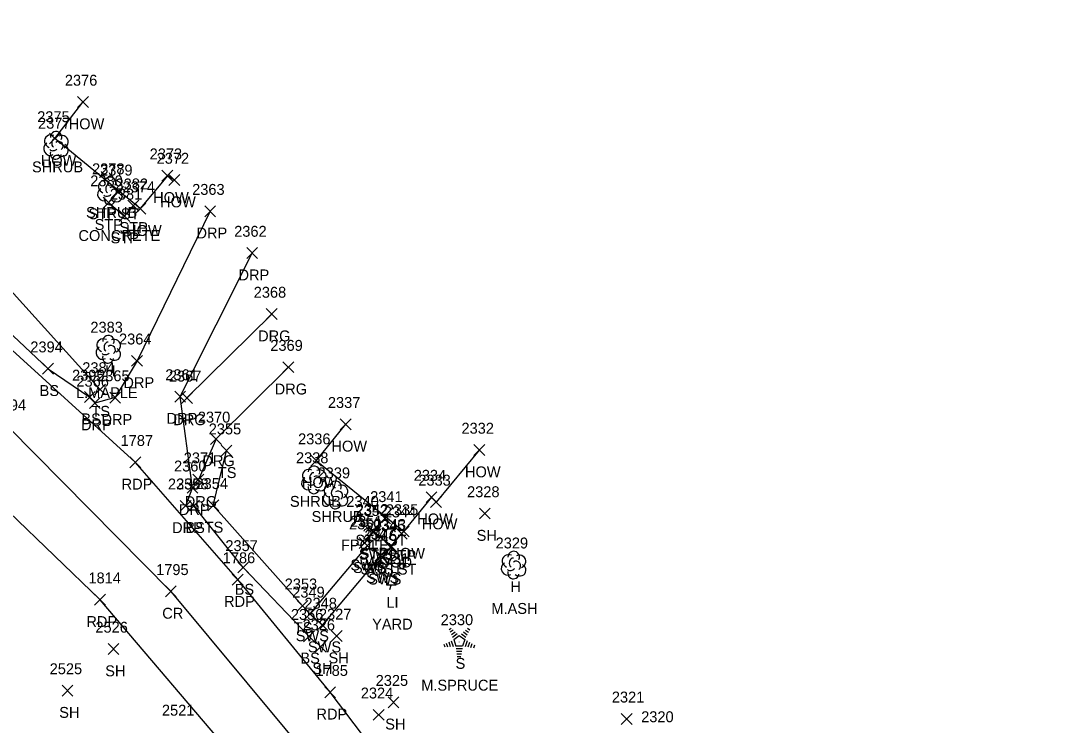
# Model space of a CAD drawing. Extents: x 1634209 to 1639641, y 608564 to 612258.
# Drawn here: x 1638878.7 to 1639067, y 611582.6 to 611711.9 of the extents above; entities that cross this region are included whole.
import ezdxf

# ---------------------------------------------------------------- set-up
doc = ezdxf.new("R2010")
doc.units = 0
for name, color, linetype in [('L_A', 7, 'Continuous'), ('L_C', 7, 'Continuous'), ('L_I', 7, 'Continuous'), ('L_TIC', 7, 'Continuous'), ('LBC', 7, 'Continuous'), ('LBF', 7, 'Continuous'), ('LELB', 7, 'Continuous'), ('LFP', 7, 'Continuous'), ('LSH', 7, 'Continuous'), ('LTC', 7, 'Continuous'), ('LTD', 7, 'Continuous'), ('P_A', 7, 'Continuous'), ('P_I', 7, 'Continuous'), ('P_TIC', 7, 'Continuous'), ('PET', 7, 'Continuous'), ('PRC', 7, 'Continuous'), ('R_A', 7, 'Continuous'), ('R_I', 7, 'Continuous'), ('R_TIC', 7, 'Continuous'), ('RDG', 7, 'Continuous'), ('RDP', 7, 'Continuous'), ('RSW', 7, 'Continuous'), ('U_A', 7, 'Continuous'), ('U_C', 7, 'Continuous'), ('U_I', 7, 'Continuous'), ('ULP', 7, 'Continuous')]:
    doc.layers.add(name, color=color, linetype=linetype)

msp = doc.modelspace()

# ---------------------------------------------------------------- linework, layer by layer
at = {"layer": 'L_TIC'}
for points in [[(1638889.13, 611695.92), (1638891.13, 611697.92)], [(1638891.13, 611695.92), (1638889.13, 611697.92)], [(1638884, 611689.23), (1638886, 611691.23)], [(1638886, 611689.23), (1638884, 611691.23)], [(1638904.62, 611682.41), (1638906.62, 611684.41)], [(1638906.62, 611682.41), (1638904.62, 611684.41)], [(1638905.9, 611681.61), (1638907.9, 611683.61)], [(1638907.9, 611681.61), (1638905.9, 611683.61)], [(1638895.54, 611679.44), (1638897.54, 611681.44)], [(1638897.54, 611679.44), (1638895.54, 611681.44)], [(1638893.81, 611677.47), (1638895.81, 611679.47)], [(1638895.81, 611677.47), (1638893.81, 611679.47)], [(1638898.37, 611676.9), (1638900.37, 611678.9)], [(1638900.37, 611676.9), (1638898.37, 611678.9)], [(1638899.64, 611676.37), (1638901.64, 611678.37)], [(1638901.64, 611676.37), (1638899.64, 611678.37)], [(1638896.75, 611675.02), (1638898.75, 611677.02)], [(1638898.75, 611675.02), (1638896.75, 611677.02)], [(1638882.74, 611647.02), (1638884.74, 611649.02)], [(1638884.74, 611647.02), (1638882.74, 611649.02)], [(1638892.27, 611643.21), (1638894.27, 611645.21)], [(1638894.27, 611643.21), (1638892.27, 611645.21)], [(1638890.39, 611641.83), (1638892.39, 611643.83)], [(1638892.39, 611641.83), (1638890.39, 611643.83)], [(1638937.3, 611636.83), (1638939.3, 611638.83)], [(1638939.3, 611636.83), (1638937.3, 611638.83)], [(1638915.45, 611631.98), (1638917.45, 611633.98)], [(1638917.45, 611631.98), (1638915.45, 611633.98)], [(1638961.79, 611632.11), (1638963.79, 611634.11)], [(1638963.79, 611632.11), (1638961.79, 611634.11)], [(1638931.88, 611630.16), (1638933.88, 611632.16)], [(1638933.88, 611630.16), (1638931.88, 611632.16)], [(1638953.04, 611623.48), (1638955.04, 611625.48)], [(1638955.04, 611623.48), (1638953.04, 611625.48)], [(1638953.88, 611622.58), (1638955.88, 611624.58)], [(1638955.88, 611622.58), (1638953.88, 611624.58)], [(1638909.47, 611621.91), (1638911.47, 611623.91)], [(1638911.47, 611621.91), (1638909.47, 611623.91)], [(1638913.03, 611621.96), (1638915.03, 611623.96)], [(1638915.03, 611621.96), (1638913.03, 611623.96)], [(1638962.82, 611620.47), (1638964.82, 611622.47)], [(1638964.82, 611620.47), (1638962.82, 611622.47)], [(1638944.49, 611619.57), (1638946.49, 611621.57)], [(1638946.49, 611619.57), (1638944.49, 611621.57)], [(1638942.42, 611617.21), (1638944.42, 611619.21)], [(1638944.42, 611617.21), (1638942.42, 611619.21)], [(1638947.55, 611616.76), (1638949.55, 611618.76)], [(1638949.55, 611616.76), (1638947.55, 611618.76)], [(1638947.92, 611617.17), (1638949.92, 611619.17)], [(1638949.92, 611617.17), (1638947.92, 611619.17)], [(1638945.66, 611614.46), (1638947.66, 611616.46)], [(1638947.66, 611614.46), (1638945.66, 611616.46)], [(1638918.5, 611610.58), (1638920.5, 611612.58)], [(1638920.5, 611610.58), (1638918.5, 611612.58)], [(1638929.38, 611603.55), (1638931.38, 611605.55)], [(1638931.38, 611603.55), (1638929.38, 611605.55)], [(1638930.56, 611597.97), (1638932.56, 611599.97)], [(1638932.56, 611597.97), (1638930.56, 611599.97)], [(1638935.66, 611598.01), (1638937.66, 611600.01)], [(1638937.66, 611598.01), (1638935.66, 611600.01)], [(1638932.71, 611596.06), (1638934.71, 611598.06)], [(1638934.71, 611596.06), (1638932.71, 611598.06)], [(1638894.73, 611595.63), (1638896.73, 611597.63)], [(1638896.73, 611595.63), (1638894.73, 611597.63)], [(1638886.29, 611588.01), (1638888.29, 611590.01)], [(1638888.29, 611588.01), (1638886.29, 611590.01)], [(1638946.06, 611585.87), (1638948.06, 611587.87)], [(1638948.06, 611585.87), (1638946.06, 611587.87)], [(1638943.33, 611583.56), (1638945.33, 611585.56)], [(1638945.33, 611583.56), (1638943.33, 611585.56)], [(1638988.8, 611582.82), (1638990.8, 611584.82)], [(1638990.8, 611582.82), (1638988.8, 611584.82)]]:
    msp.add_lwpolyline(points, dxfattribs=at)
at = {"layer": 'LBC'}
for points in [[(1638906.9, 611682.61), (1638905.62, 611683.41), (1638900.64, 611677.37), (1638885, 611690.23), (1638890.13, 611696.92)], [(1638962.79, 611633.11), (1638954.88, 611623.58), (1638954.04, 611624.48), (1638948.92, 611618.17), (1638932.88, 611631.16), (1638938.3, 611637.83)]]:
    msp.add_lwpolyline(points, dxfattribs=at)
at = {"layer": 'LBF'}
for points in [[(1638896.54, 611680.44), (1638894.81, 611678.47), (1638897.75, 611676.02), (1638899.37, 611677.9)], [(1638945.49, 611620.57), (1638943.42, 611618.21), (1638946.66, 611615.46), (1638948.55, 611617.76)]]:
    msp.add_lwpolyline(points, dxfattribs=at)
at = {"layer": 'LELB'}
for points in [[(1638873.21, 611711.86), (1638857.7, 611692.03), (1638852.16, 611680.32), (1638857.49, 611671.46), (1638870.87, 611660.12), (1638883.74, 611648.02), (1638891.39, 611642.83)], [(1638893.27, 611644.21), (1638875.11, 611664.31), (1638860.57, 611677.05), (1638859.03, 611684.68), (1638875.95, 611708.58)], [(1638930.38, 611604.55), (1638914.03, 611622.96), (1638916.45, 611632.98)], [(1638931.56, 611598.97), (1638919.5, 611611.58), (1638910.47, 611622.91)]]:
    msp.add_lwpolyline(points, dxfattribs=at)
at = {"layer": 'LFP'}
for radius in [0.625, 0.0833]:
    msp.add_circle((1638941.77, 611619.69), radius, dxfattribs=at)
at = {"layer": 'LSH'}
for p, q in [((1638885.16, 611689.03), (1638885.16, 611689.03)), ((1638885.16, 611689.03), (1638885.16, 611689.03)), ((1638895.06, 611680.68), (1638895.06, 611680.68)), ((1638895.06, 611680.68), (1638895.06, 611680.68)), ((1638932.45, 611627.7), (1638932.45, 611627.7)), ((1638932.45, 611627.7), (1638932.45, 611627.7)), ((1638936.42, 611624.92), (1638936.42, 611624.92)), ((1638936.42, 611624.92), (1638936.42, 611624.92))]:
    msp.add_line(p, q, dxfattribs=at)
for centre in [(1638885.2, 611690.46), (1638895.1, 611682.12), (1638932.5, 611629.13), (1638936.46, 611626.36)]:
    msp.add_arc(centre, 1.05, 335.5272, 180.9563, dxfattribs=at)
for centre, major_axis, ratio, start_param, end_param in [((1638884.36, 611689.69), (1.21, -0.51), 0.895232, 1.570796, 4.712389), ((1638884.95, 611689.48), (-0.208, -0.792), 0.645439, 3.141593, 6.283185), ((1638886.2, 611689.61), (-1.14, -0.48), 0.949671, 1.570796, 4.712389), ((1638884.07, 611688.32), (0.58, -1.04), 0.959034, 3.141593, 6.283185), ((1638884.7, 611688.28), (-0.625, -0.083), 0.423636, 0, 3.141593), ((1638885.66, 611688.86), (-0.5, 0.667), 0.989748, 3.141593, 6.283185), ((1638886.16, 611688.19), (-1.09, 0.79), 0.841452, 1.570796, 4.712389), ((1638885.16, 611687.53), (0.26, 1.06), 0.942809, 1.570796, 4.712389), ((1638894.26, 611681.35), (1.21, -0.51), 0.895232, 1.570796, 4.712389), ((1638893.97, 611679.98), (0.58, -1.04), 0.959034, 3.141593, 6.283185), ((1638894.85, 611681.14), (-0.208, -0.792), 0.645439, 3.141593, 6.283185), ((1638895.56, 611680.52), (-0.5, 0.667), 0.989748, 3.141593, 6.283185), ((1638896.1, 611681.27), (-1.14, -0.48), 0.949671, 1.570796, 4.712389), ((1638895.06, 611679.18), (0.26, 1.06), 0.942809, 1.570796, 4.712389), ((1638894.6, 611679.93), (-0.625, -0.083), 0.423636, 0, 3.141593), ((1638896.06, 611679.85), (-1.09, 0.79), 0.841452, 1.570796, 4.712389), ((1638931.66, 611628.36), (1.21, -0.51), 0.895232, 1.570796, 4.712389), ((1638932.24, 611628.16), (-0.208, -0.792), 0.645439, 3.141593, 6.283185), ((1638932.95, 611627.53), (-0.5, 0.667), 0.989748, 3.141593, 6.283185), ((1638933.49, 611628.28), (-1.14, -0.48), 0.949671, 1.570796, 4.712389), ((1638931.37, 611626.99), (0.58, -1.04), 0.959034, 3.141593, 6.283185), ((1638932.45, 611626.2), (0.26, 1.06), 0.942809, 1.570796, 4.712389), ((1638931.99, 611626.95), (-0.625, -0.083), 0.423636, 0, 3.141593), ((1638933.45, 611626.86), (-1.09, 0.79), 0.841452, 1.570796, 4.712389), ((1638935.62, 611625.59), (1.21, -0.51), 0.895232, 1.570796, 4.712389), ((1638936.21, 611625.38), (-0.208, -0.792), 0.645439, 3.141593, 6.283185), ((1638937.46, 611625.51), (-1.14, -0.48), 0.949671, 1.570796, 4.712389), ((1638935.33, 611624.22), (0.58, -1.04), 0.959034, 3.141593, 6.283185), ((1638936.92, 611624.76), (-0.5, 0.667), 0.989748, 3.141593, 6.283185), ((1638937.42, 611624.09), (-1.09, 0.79), 0.841452, 1.570796, 4.712389), ((1638936.42, 611623.42), (0.26, 1.06), 0.942809, 1.570796, 4.712389), ((1638935.96, 611624.17), (-0.625, -0.083), 0.423636, 0, 3.141593)]:
    msp.add_ellipse(centre, major_axis=major_axis, ratio=ratio, start_param=start_param, end_param=end_param, dxfattribs=at)
at = {"layer": 'LTC'}
for p, q in [((1638957.26, 611600.21), (1638957.62, 611600.47)), ((1638957.47, 611599.75), (1638958, 611600.13)), ((1638960.29, 611600.1), (1638960.84, 611599.71)), ((1638960.66, 611600.45), (1638961.08, 611600.15)), ((1638957.66, 611598.14), (1638957.99, 611597.12)), ((1638957.68, 611599.28), (1638958.38, 611599.79)), ((1638957.89, 611598.82), (1638958.77, 611599.45)), ((1638958.11, 611598.36), (1638959.13, 611599.1)), ((1638958.11, 611598.36), (1638958.5, 611597.17)), ((1638959.13, 611599.1), (1638960.12, 611598.37)), ((1638959.55, 611599.41), (1638960.36, 611598.82)), ((1638960.12, 611598.37), (1638959.73, 611597.17)), ((1638959.92, 611599.76), (1638960.6, 611599.26)), ((1638960.56, 611598.1), (1638960.22, 611597.06)), ((1638956.29, 611597.49), (1638956.45, 611597.02)), ((1638956.75, 611597.71), (1638956.96, 611597.06)), ((1638957.2, 611597.93), (1638957.48, 611597.09)), ((1638959.73, 611597.17), (1638958.5, 611597.17)), ((1638959.69, 611596.67), (1638958.55, 611596.67)), ((1638959.61, 611596.17), (1638958.62, 611596.17)), ((1638961.01, 611597.85), (1638960.72, 611596.96)), ((1638961.45, 611597.6), (1638961.21, 611596.87)), ((1638961.89, 611597.35), (1638961.71, 611596.77)), ((1638959.53, 611595.67), (1638958.69, 611595.67)), ((1638959.44, 611595.17), (1638958.77, 611595.17))]:
    msp.add_line(p, q, dxfattribs=at)
at = {"layer": 'LTD'}
for p, q in [((1638894.75, 611651.63), (1638894.75, 611651.63)), ((1638894.75, 611651.63), (1638894.75, 611651.63)), ((1638969.06, 611612.07), (1638969.06, 611612.07)), ((1638969.06, 611612.07), (1638969.06, 611612.07))]:
    msp.add_line(p, q, dxfattribs=at)
for centre in [(1638894.8, 611653.06), (1638969.11, 611613.5)]:
    msp.add_arc(centre, 1.05, 335.5272, 180.9563, dxfattribs=at)
for centre, major_axis, ratio, start_param, end_param in [((1638893.96, 611652.29), (1.21, -0.51), 0.895232, 1.570796, 4.712389), ((1638894.54, 611652.08), (-0.208, -0.792), 0.645439, 3.141593, 6.283185), ((1638895.79, 611652.21), (-1.14, -0.48), 0.949671, 1.570796, 4.712389), ((1638893.67, 611650.92), (0.58, -1.04), 0.959034, 3.141593, 6.283185), ((1638894.29, 611650.88), (-0.625, -0.083), 0.423636, 0, 3.141593), ((1638895.25, 611651.46), (-0.5, 0.667), 0.989748, 3.141593, 6.283185), ((1638895.75, 611650.79), (-1.09, 0.79), 0.841452, 1.570796, 4.712389), ((1638894.75, 611650.13), (0.26, 1.06), 0.942809, 1.570796, 4.712389), ((1638968.27, 611612.73), (1.21, -0.51), 0.895232, 1.570796, 4.712389), ((1638968.85, 611612.52), (-0.208, -0.792), 0.645439, 3.141593, 6.283185), ((1638970.1, 611612.65), (-1.14, -0.48), 0.949671, 1.570796, 4.712389), ((1638967.98, 611611.36), (0.58, -1.04), 0.959034, 3.141593, 6.283185), ((1638968.6, 611611.32), (-0.625, -0.083), 0.423636, 0, 3.141593), ((1638969.56, 611611.9), (-0.5, 0.667), 0.989748, 3.141593, 6.283185), ((1638970.06, 611611.23), (-1.09, 0.79), 0.841452, 1.570796, 4.712389), ((1638969.06, 611610.57), (0.26, 1.06), 0.942809, 1.570796, 4.712389)]:
    msp.add_ellipse(centre, major_axis=major_axis, ratio=ratio, start_param=start_param, end_param=end_param, dxfattribs=at)
at = {"layer": 'P_TIC'}
for points in [[(1638898.72, 611629.86), (1638900.72, 611631.86)], [(1638900.72, 611629.86), (1638898.72, 611631.86)], [(1638917.51, 611608.36), (1638919.51, 611610.36)], [(1638919.51, 611608.36), (1638917.51, 611610.36)], [(1638905.24, 611606.19), (1638907.24, 611608.19)], [(1638907.24, 611606.19), (1638905.24, 611608.19)], [(1638892.27, 611604.66), (1638894.27, 611606.66)], [(1638894.27, 611604.66), (1638892.27, 611606.66)], [(1638934.46, 611587.7), (1638936.46, 611589.7)], [(1638936.46, 611587.7), (1638934.46, 611589.7)]]:
    msp.add_lwpolyline(points, dxfattribs=at)
at = {"layer": 'PET'}
for points in [[(1639148.64, 611331.08), (1639142.07, 611329.18), (1639135.69, 611328.74), (1639125.69, 611331.14), (1639119.17, 611334.87), (1639114.18, 611340.56), (1639098.76, 611361.78), (1639080.31, 611387.33), (1639061.61, 611413.48), (1639039.15, 611444.21), (1639014.33, 611480.36), (1638988.41, 611516.9), (1638963.39, 611551.84), (1638935.46, 611588.7), (1638918.51, 611609.36), (1638899.72, 611630.86), (1638874.4, 611653.86), (1638846.55, 611674.46), (1638833.14, 611682.53), (1638823.86, 611689.16)], [(1639117.36, 611283.37), (1639114.12, 611301.89), (1639095.51, 611328.5), (1639070.51, 611363.26), (1639041.38, 611404.69), (1639011.57, 611446.4), (1638984.33, 611485.14), (1638954.17, 611527.49), (1638934.32, 611554.77), (1638918.88, 611575.58), (1638893.27, 611605.66), (1638868.11, 611629.83), (1638836.66, 611652.85), (1638812.43, 611667.63)]]:
    msp.add_lwpolyline(points, dxfattribs=at)
at = {"layer": 'PRC'}
msp.add_lwpolyline([(1638818.79, 611678.83), (1638843.97, 611663.34), (1638876.43, 611637.38), (1638906.24, 611607.19), (1638934.14, 611573.69), (1638965.3, 611531.42), (1638998.82, 611484.34), (1639033.82, 611434.48), (1639068.01, 611386.3), (1639093.94, 611350.49), (1639111.89, 611325.37), (1639129.22, 611302.76)], dxfattribs=at)
at = {"layer": 'R_TIC'}
for points in [[(1638912.45, 611675.9), (1638914.45, 611677.9)], [(1638914.45, 611675.9), (1638912.45, 611677.9)], [(1638920.16, 611668.22), (1638922.16, 611670.22)], [(1638922.16, 611668.22), (1638920.16, 611670.22)], [(1638923.75, 611657.04), (1638925.75, 611659.04)], [(1638925.75, 611657.04), (1638923.75, 611659.04)], [(1638899.05, 611648.47), (1638901.05, 611650.47)], [(1638901.05, 611648.47), (1638899.05, 611650.47)], [(1638926.79, 611647.3), (1638928.79, 611649.3)], [(1638928.79, 611647.3), (1638926.79, 611649.3)], [(1638895.04, 611641.73), (1638897.04, 611643.73)], [(1638897.04, 611641.73), (1638895.04, 611643.73)], [(1638906.96, 611641.92), (1638908.96, 611643.92)], [(1638908.96, 611641.92), (1638906.96, 611643.92)], [(1638908.2, 611641.67), (1638910.2, 611643.67)], [(1638910.2, 611641.67), (1638908.2, 611643.67)], [(1638891.3, 611640.73), (1638893.3, 611642.73)], [(1638893.3, 611640.73), (1638891.3, 611642.73)], [(1638913.54, 611634.15), (1638915.54, 611636.15)], [(1638915.54, 611634.15), (1638913.54, 611636.15)], [(1638910.3, 611626.67), (1638912.3, 611628.67)], [(1638912.3, 611626.67), (1638910.3, 611628.67)], [(1638909.22, 611625.18), (1638911.22, 611627.18)], [(1638911.22, 611625.18), (1638909.22, 611627.18)], [(1638907.98, 611621.88), (1638909.98, 611623.88)], [(1638909.98, 611621.88), (1638907.98, 611623.88)], [(1638942.35, 611617.03), (1638944.35, 611619.03)], [(1638944.35, 611617.03), (1638942.35, 611619.03)], [(1638940.79, 611615.05), (1638942.79, 611617.05)], [(1638942.79, 611615.05), (1638940.79, 611617.05)], [(1638941.27, 611614.57), (1638943.27, 611616.57)], [(1638943.27, 611614.57), (1638941.27, 611616.57)], [(1638945.53, 611614.28), (1638947.53, 611616.28)], [(1638947.53, 611614.28), (1638945.53, 611616.28)], [(1638943.66, 611612.73), (1638945.66, 611614.73)], [(1638945.66, 611612.73), (1638943.66, 611614.73)], [(1638944.06, 611612.46), (1638946.06, 611614.46)], [(1638946.06, 611612.46), (1638944.06, 611614.46)], [(1638930.77, 611602.06), (1638932.77, 611604.06)], [(1638932.77, 611602.06), (1638930.77, 611604.06)], [(1638933, 611600.02), (1638935, 611602.02)], [(1638935, 611600.02), (1638933, 611602.02)]]:
    msp.add_lwpolyline(points, dxfattribs=at)
at = {"layer": 'RDG'}
for points in [[(1638909.2, 611642.67), (1638924.75, 611658.04)], [(1638927.79, 611648.3), (1638914.54, 611635.15), (1638911.3, 611627.67)]]:
    msp.add_lwpolyline(points, dxfattribs=at)
at = {"layer": 'RDP'}
for points in [[(1638913.45, 611676.9), (1638900.05, 611649.47), (1638896.04, 611642.73), (1638892.3, 611641.73)], [(1638908.98, 611622.88), (1638910.22, 611626.18), (1638907.96, 611642.92), (1638921.16, 611669.22)]]:
    msp.add_lwpolyline(points, dxfattribs=at)
at = {"layer": 'RSW'}
msp.add_lwpolyline([(1638946.53, 611615.28), (1638945.06, 611613.46), (1638944.66, 611613.73), (1638934, 611601.02), (1638931.77, 611603.06), (1638942.27, 611615.57), (1638941.79, 611616.05), (1638943.35, 611618.03)], dxfattribs=at)
at = {"layer": 'ULP'}
for p, q in [((1638945.82, 611608.35), (1638945.82, 611610.02)), ((1638945.82, 611610.02), (1638947.49, 611610.02)), ((1638946.82, 611610.85), (1638946.66, 611610.02)), ((1638947.49, 611610.02), (1638947.49, 611608.35)), ((1638947.49, 611608.35), (1638945.82, 611608.35)), ((1638946.41, 611607.52), (1638946.66, 611608.35)), ((1638946.66, 611609.19), (1638946.66, 611609.19))]:
    msp.add_line(p, q, dxfattribs=at)

# ---------------------------------------------------------------- texts
at = {"layer": 'L_A'}
for s, p in [('HOW', (1638887.51, 611691.92)), ('HOW', (1638882.39, 611685.23)), ('SHRUB', (1638880.79, 611684.03)), ('HOW', (1638903, 611678.41)), ('HOW', (1638904.28, 611677.61)), ('SHRUB', (1638890.69, 611675.68)), ('STP ST', (1638891.13, 611675.44)), ('STP', (1638892.27, 611673.47)), ('STP', (1638896.83, 611672.9)), ('HOW', (1638898.03, 611672.37)), ('STP', (1638895.2, 611671.02)), ('H', (1638894.18, 611646.63)), ('BS', (1638882.18, 611643.02)), ('BS', (1638889.83, 611637.83)), ('TS', (1638891.68, 611639.21)), ('HOW', (1638935.69, 611632.83)), ('TS', (1638914.86, 611627.98)), ('HOW', (1638960.17, 611628.11)), ('HOW', (1638930.27, 611626.16)), ('SHRUB', (1638928.08, 611622.7)), ('SHRUB', (1638932.05, 611619.92)), ('HOW', (1638951.42, 611619.48)), ('HOW', (1638952.26, 611618.58)), ('BS', (1638908.91, 611617.91)), ('TS', (1638912.44, 611617.96)), ('STP ST', (1638940.08, 611615.57)), ('SH', (1638962.31, 611616.47)), ('FPOLE', (1638937.44, 611614.69)), ('STP', (1638940.88, 611613.21)), ('HOW', (1638946.31, 611613.17)), ('STP', (1638946.01, 611612.76)), ('STP', (1638944.12, 611610.46)), ('BS', (1638917.94, 611606.58)), ('H', (1638968.49, 611607.07)), ('TS', (1638928.79, 611599.55)), ('BS', (1638930, 611593.97)), ('SH', (1638935.15, 611594.01)), ('S', (1638958.45, 611593)), ('SH', (1638894.21, 611591.63)), ('SH', (1638932.19, 611592.06)), ('SH', (1638885.78, 611584.01)), ('SH', (1638945.55, 611581.87))]:
    msp.add_text(s, height=2, dxfattribs=at).set_placement(p)
at = {"layer": 'L_C'}
for s, p in [('CONCRETE', (1638889.3, 611671.44)), ('L.MAPLE', (1638888.86, 611642.63)), ('WOOD', (1638941.84, 611611.57)), ('M.ASH', (1638965.01, 611603.07)), ('M.SPRUCE', (1638952.15, 611589))]:
    msp.add_text(s, height=2, dxfattribs=at).set_placement(p)
at = {"layer": 'L_I'}
for s, p in [('2376', (1638886.81, 611699.92)), ('2375', (1638881.74, 611693.23)), ('2377', (1638881.9, 611692.03)), ('2373', (1638902.36, 611686.41)), ('2372', (1638903.64, 611685.61)), ('2378', (1638891.8, 611683.68)), ('2379', (1638893.27, 611683.44)), ('2380', (1638891.47, 611681.47)), ('2382', (1638896.11, 611680.9)), ('2381', (1638895.05, 611679.02)), ('2374', (1638897.38, 611680.37)), ('2383', (1638891.49, 611654.63)), ('2394', (1638880.48, 611651.02)), ('2384', (1638890.01, 611647.21)), ('2395', (1638888.13, 611645.83)), ('2337', (1638935.04, 611640.83)), ('2355', (1638913.19, 611635.98)), ('2332', (1638959.53, 611636.11)), ('2336', (1638929.57, 611634.16)), ('2338', (1638929.19, 611630.7)), ('2339', (1638933.15, 611627.92)), ('2334', (1638950.78, 611627.48)), ('2333', (1638951.62, 611626.58)), ('2358', (1638907.21, 611625.91)), ('2354', (1638910.77, 611625.96)), ('2328', (1638960.56, 611624.47)), ('2340', (1638938.42, 611622.69)), ('2341', (1638942.79, 611623.57)), ('2342', (1638940.16, 611621.21)), ('2344', (1638945.29, 611620.76)), ('2335', (1638945.66, 611621.17)), ('2343', (1638943.4, 611618.46)), ('2329', (1638965.79, 611615.07)), ('2357', (1638916.24, 611614.58)), ('2353', (1638927.12, 611607.55)), ('2356', (1638928.25, 611601.97)), ('2327', (1638933.4, 611602.01)), ('2326', (1638930.39, 611600.06)), ('2330', (1638955.72, 611601)), ('2526', (1638892.41, 611599.63)), ('2525', (1638884.03, 611592.01)), ('2325', (1638943.8, 611589.87)), ('2324', (1638941.07, 611587.56)), ('2321', (1638987.1, 611586.82)), ('2521', (1638904.61, 611584.41)), ('2320', (1638992.48, 611583.21))]:
    msp.add_text(s, height=2, dxfattribs=at).set_placement(p)
at = {"layer": 'LTC'}
msp.add_text('.', height=1.04, rotation=270, dxfattribs=at).set_placement((1638959.01, 611598.11))
at = {"layer": 'P_A'}
for s, p in [('RDP', (1638897.21, 611625.86)), ('RDP', (1638916, 611604.36)), ('CR', (1638904.67, 611602.19)), ('RDP', (1638890.76, 611600.66)), ('RDP', (1638932.94, 611583.7))]:
    msp.add_text(s, height=2, dxfattribs=at).set_placement(p)
at = {"layer": 'P_I'}
for s, p in [('1794', (1638873.74, 611640.38)), ('1787', (1638897.03, 611633.86)), ('1786', (1638915.76, 611612.36)), ('1795', (1638903.55, 611610.19)), ('1814', (1638891.14, 611608.66)), ('1785', (1638932.76, 611591.7))]:
    msp.add_text(s, height=2, dxfattribs=at).set_placement(p)
at = {"layer": 'R_A'}
for s, p in [('DRP', (1638910.94, 611671.9)), ('DRP', (1638918.65, 611664.22)), ('DRG', (1638922.24, 611653.04)), ('DRP', (1638897.54, 611644.47)), ('DRG', (1638925.28, 611643.3)), ('DRP', (1638893.52, 611637.73)), ('DRP', (1638905.45, 611637.92)), ('DRG', (1638906.69, 611637.67)), ('DRP', (1638889.78, 611636.73)), ('DRG', (1638912.03, 611630.15)), ('DRG', (1638908.79, 611622.67)), ('DRP', (1638907.71, 611621.18)), ('DRP', (1638906.47, 611617.88)), ('SWS', (1638940.72, 611613.03)), ('SWS', (1638939.16, 611611.05)), ('SWS', (1638939.64, 611610.57)), ('SWS ST', (1638941.03, 611610.28)), ('SWS', (1638942.03, 611608.73)), ('SWS', (1638942.43, 611608.46)), ('SWS', (1638929.14, 611598.06)), ('SWS', (1638931.37, 611596.02))]:
    msp.add_text(s, height=2, dxfattribs=at).set_placement(p)
at = {"layer": 'R_I'}
for s, p in [('2363', (1638910.15, 611679.9)), ('2362', (1638917.86, 611672.22)), ('2368', (1638921.44, 611661.04)), ('2364', (1638896.74, 611652.47)), ('2369', (1638924.48, 611651.3)), ('2365', (1638892.73, 611645.73)), ('2361', (1638905.22, 611645.92)), ('2367', (1638905.89, 611645.67)), ('2366', (1638888.93, 611644.73)), ('2370', (1638911.19, 611638.15)), ('2371', (1638908.61, 611630.67)), ('2360', (1638906.83, 611629.18)), ('2359', (1638905.71, 611625.88)), ('2352', (1638940.09, 611621.03)), ('2350', (1638938.92, 611618.57)), ('2351', (1638939.09, 611619.05)), ('2347', (1638941.4, 611616.73)), ('2345', (1638943.27, 611618.28)), ('2346', (1638941.74, 611616.46)), ('2349', (1638928.5, 611606.06)), ('2348', (1638930.74, 611604.02))]:
    msp.add_text(s, height=2, dxfattribs=at).set_placement(p)
at = {"layer": 'U_A'}
msp.add_text('LI', height=2, dxfattribs=at).set_placement((1638945.76, 611604.19))
at = {"layer": 'U_C'}
msp.add_text('YARD', height=2, dxfattribs=at).set_placement((1638943.15, 611600.19))
at = {"layer": 'U_I'}
msp.add_text('2331', height=2, dxfattribs=at).set_placement((1638943.96, 611612.19))

doc.saveas('drawing.dxf')
